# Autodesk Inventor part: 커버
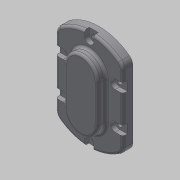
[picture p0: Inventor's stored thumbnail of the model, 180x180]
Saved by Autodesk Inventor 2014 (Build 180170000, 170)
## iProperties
Created: 2019-03
Part Number: 커버
Material: 알루미늄 6061
Document SubType Name: Modeling
Designer: mduedu
Density: 1 g/cm^3
Appearance: 기본값
Author: mduedu
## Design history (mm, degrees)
sketch "스케치1"
  geometry: L1 (44.721, -40)-(-44.721, -40); L2 (44.721, 40)-(-44.721, 40); A1 r 60 centre (0, 0) between (44.721, -40) and (44.721, 40); A2 r 60 centre (0, 0) between (-44.721, 40) and (-44.721, -40); 5 further points
  constraints: 6 point on circle, 4 end point, 2 centre point, 2 coincident, 2 horizontal alignment, 2 midpoint, 2 vertical alignment, 1 horizontal, 1 parallel
  dimensions: "d0" = 60 radius of A1; "d2" = 80 distance between parallel lines of L2 L1; "d3" = 120 distance of point (-60, 0) point (60, 0) (derived)
extrude "돌출1" new body sketch "스케치1" distance "d4" = 12; taper "d5" = 0 deg
sketch "스케치2"
  geometry: L1 (-20, -22)-(20, -22); L2 (20, -22)-(20, 22); L3 (20, 22)-(-20, 22); L4 (-20, 22)-(-20, -22); L5 (-20, -22)-(20, 22); L6 (20, -22)-(-20, 22); 3 further points
  constraints: 12 end point, 4 midpoint, 2 horizontal alignment, 2 parallel, 1 horizontal, 1 perpendicular, 4 other
  dimensions: "d6" = 40 distance between parallel lines of L2 L4; "d8" = 44 distance between parallel lines of L1 L3
extrude "돌출2" join sketch "스케치2" distance "d9" = 10; taper "d10" = 0 deg
fillet "모깎기1" dims "d11" = 10
fillet "모깎기2" dims "d12" = 3
sketch "스케치3"
  geometry: L1 (31, -22)-(31, 22); L2 (-31, 22)-(-31, -22); L3 (-31, -22)-(31, 22); L4 (31, -22)-(-31, 22); A1 r 31 centre (0, 22) between (31, 22) and (-31, 22); A2 r 31 centre (0, -22) between (-31, -22) and (31, -22); 7 further points
  constraints: 8 end point, 6 point on circle, 4 coincident, 3 tangent, 2 centre point, 2 midpoint, 1 parallel, 1 vertical, 1 vertical alignment
  dimensions: "d13" = 31 radius of A1; "d15" = 44 distance of A2.centre A1.centre
hole "구멍2" sketch "스케치3" at (-31, 22), (-31, -22), (31, -22), (31, 22), (0, 53), (0, -53) diameter "d28" = 5.5; stored, may be unused: countersink angle "d32" = 90 deg, drill point angle "d34" = 118 deg; dims "d29" = 6, "d30" = 4, "d31" = 2, "d33" = 8
sketch "스케치5"
  geometry: L1 (-40, 40)-(-40, -40) reference; L2 (40, -40)-(40, 40) reference; L3 (-5.5, 53)-(-5.5, 59.747); L4 (5.5, 53)-(5.5, 59.747); L5 (-31, 27.5)-(-40, 27.5); L6 (-31, 16.5)-(-40, 16.5); L7 (-31, -16.5)-(-40, -16.5); L8 (-31, -27.5)-(-40, -27.5); L9 (-5.5, -53)-(-5.5, -59.747); L10 (5.5, -53)-(5.5, -59.747); L11 (31, -27.5)-(40, -27.5); L12 (31, -16.5)-(40, -16.5); L13 (31, 16.5)-(40, 16.5); L14 (31, 27.5)-(40, 27.5); C1 r 2.75 at (0, 53) reference; C2 r 2.75 at (-31, 22) reference; C3 r 2.75 at (-31, -22) reference; C4 r 2.75 at (0, -53) reference; C5 r 2.75 at (31, -22) reference; C6 r 2.75 at (31, 22) reference; A1 r 60 centre (0, 0) between (36, 48) and (-36, 48) reference; A2 r 10 centre (-30, 40) between (-36, 48) and (-40, 40) reference; A3 r 10 centre (-30, -40) between (-40, -40) and (-36, -48) reference; A4 r 60 centre (0, 0) between (-36, -48) and (36, -48) reference; A5 r 10 centre (30, -40) between (36, -48) and (40, -40) reference; A6 r 10 centre (30, 40) between (40, 40) and (36, 48) reference; A7 r 5.5 centre (0, 53) between (-5.5, 53) and (5.5, 53); A8 r 5.5 centre (-31, 22) between (-31, 16.5) and (-31, 27.5); A9 r 5.5 centre (-31, -22) between (-31, -27.5) and (-31, -16.5); A10 r 5.5 centre (0, -53) between (5.5, -53) and (-5.5, -53); A11 r 5.5 centre (31, -22) between (31, -16.5) and (31, -27.5); A12 r 5.5 centre (31, 22) between (31, 27.5) and (31, 16.5); 1 further point
  constraints: 24 end point, 16 point on circle, 12 tangent, 8 parallel, 8 point on line, 6 centre point, 5 concentric, 4 horizontal, 1 coincident, 1 vertical
  dimensions: "d35" = 11 diameter of A7; "d36" = 11 diameter of A8; "d37" = 11 diameter of A9; "d38" = 11 diameter of A10; "d39" = 11 diameter of A11; "d40" = 11 diameter of A12
extrude "돌출4" cut sketch "스케치5" distance "d41" = 5.4; taper "d42" = 0 deg
sketch "스케치6"
  geometry: C1 r 12.5 at (0, 22); 1 further point
  constraints: 1 centre point, 1 vertical alignment
  dimensions: "d43" = 25 diameter of C1; "d45" = 22 distance of C1.centre point (0, 0)
extrude "돌출5" cut sketch "스케치6" distance "d47" = 15; taper "d48" = 0 deg
node "솔리드1"
mirror "대칭1"
